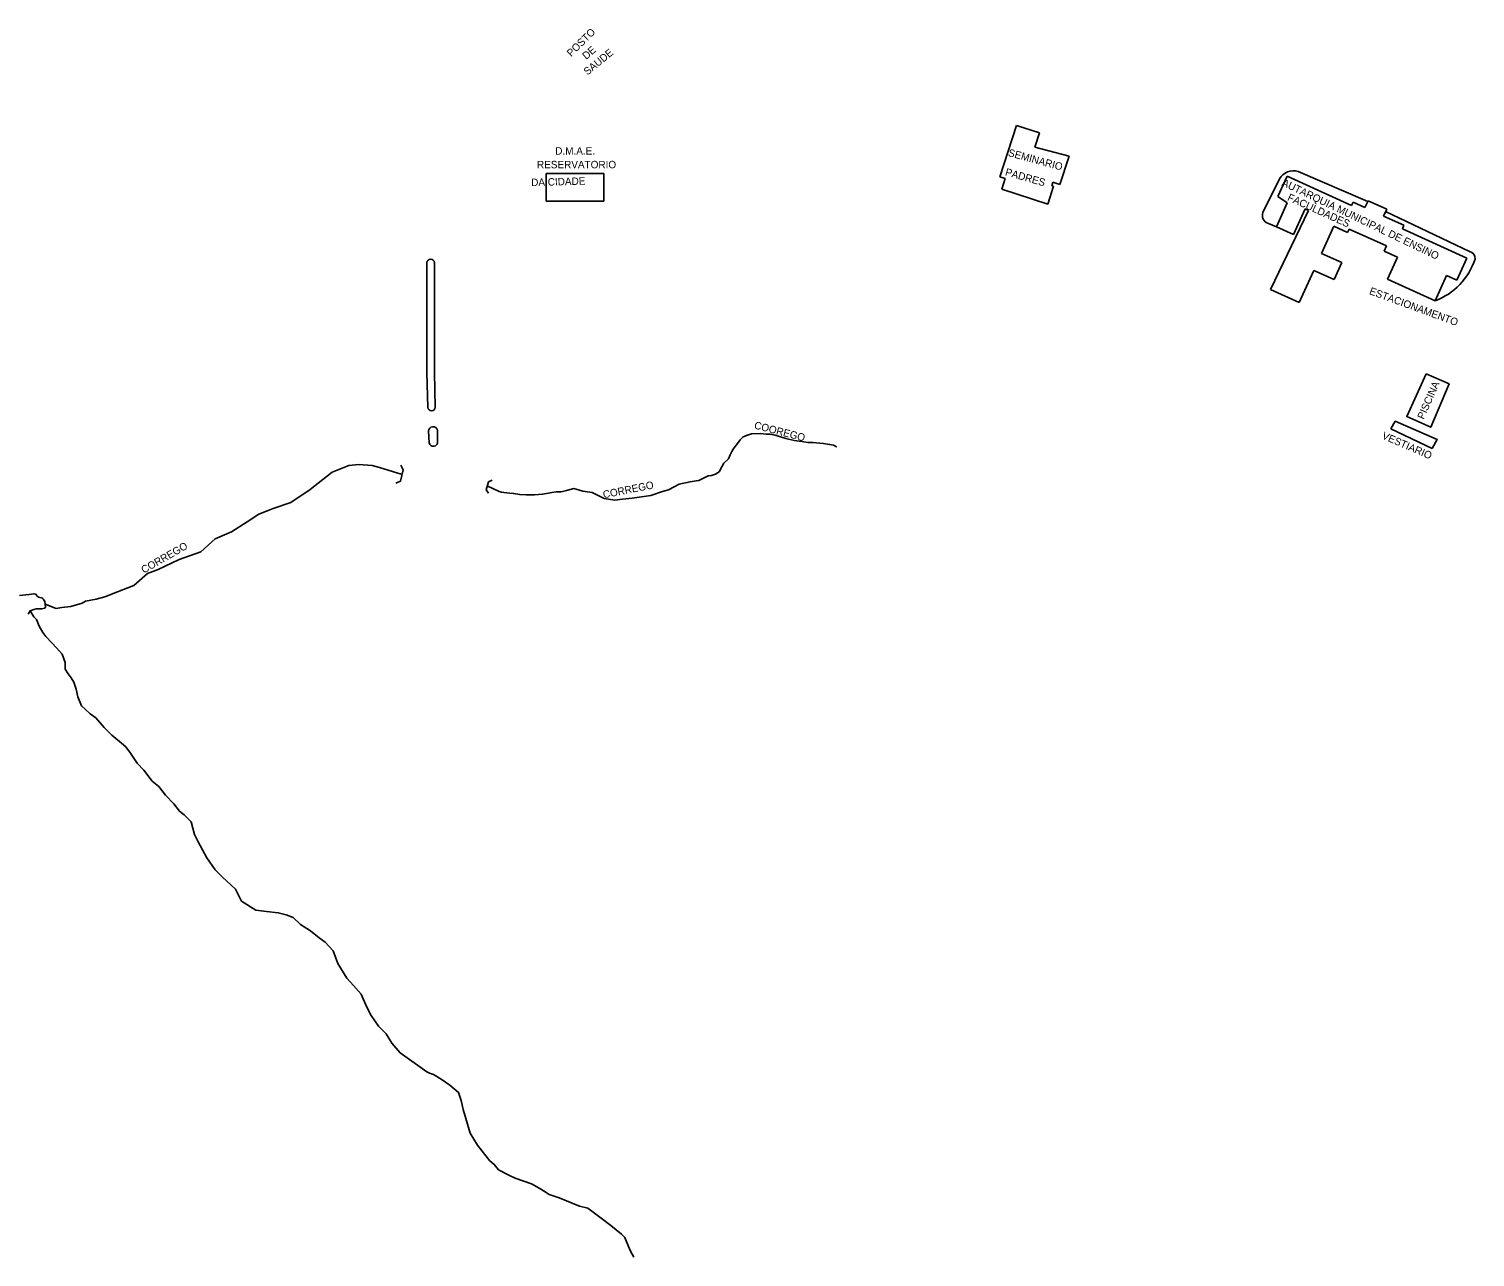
# Model space of a CAD drawing. Extents: x 325899 to 363134, y 7578590 to 7592502.
# Drawn here: x 334117 to 334893, y 7588027 to 7588686 of the extents above; entities that cross this region are included whole.
import ezdxf

# ---------------------------------------------------------------- set-up
doc = ezdxf.new("R2010")
doc.units = 0
for name, color, linetype in [('EDIFEXISTENT', 7, 'Continuous'), ('EDIFIDENTIF', 7, 'Continuous'), ('EDIFOBRAEXIS', 7, 'Continuous')]:
    doc.layers.add(name, color=color, linetype=linetype)

msp = doc.modelspace()

# ---------------------------------------------------------------- linework, layer by layer
at = {"layer": 'EDIFEXISTENT'}
for p, q in [((334638.12, 7588607.06), (334647.04, 7588634.65)), ((334647.04, 7588634.65), (334659.41, 7588630.66)), ((334659.41, 7588630.66), (334656.95, 7588623.04)), ((334656.95, 7588623.04), (334675.33, 7588618.15)), ((334675.33, 7588618.15), (334670.42, 7588602.93)), ((334394.39, 7588608.91), (334425.39, 7588608.91)), ((334394.39, 7588593.91), (334394.39, 7588608.91)), ((334425.39, 7588608.91), (334425.39, 7588593.91)), ((334640.98, 7588606.14), (334638.12, 7588607.06)), ((334639.13, 7588600.43), (334640.98, 7588606.14)), ((334787.52, 7588596.4), (334792.48, 7588607.33)), ((334792.48, 7588607.33), (334827.08, 7588591.6)), ((334663.87, 7588592.43), (334639.13, 7588600.43)), ((334666.95, 7588601.95), (334663.87, 7588592.43)), ((334666.61, 7588604.16), (334665.99, 7588602.26)), ((334665.99, 7588602.26), (334666.95, 7588601.95)), ((334670.42, 7588602.93), (334666.61, 7588604.16)), ((334425.39, 7588593.91), (334394.39, 7588593.91)), ((334786.77, 7588580.26), (334792.56, 7588593.01)), ((334792.56, 7588593.01), (334787.52, 7588596.4)), ((334827.08, 7588591.6), (334827.9, 7588593.42)), ((334827.9, 7588593.42), (334834.28, 7588590.53)), ((334834.28, 7588590.53), (334835.93, 7588594.17)), ((334835.93, 7588594.17), (334845.94, 7588589.62)), ((334783.54, 7588546.58), (334803.9, 7588588.95)), ((334802.08, 7588589.78), (334795.87, 7588576.13)), ((334803.9, 7588588.95), (334802.08, 7588589.78)), ((334845.94, 7588589.62), (334844.29, 7588585.97)), ((334844.29, 7588585.97), (334855.21, 7588581.01)), ((334795.87, 7588576.13), (334786.77, 7588580.26)), ((334817.64, 7588580.51), (334811.02, 7588565.95)), ((334824.92, 7588577.2), (334817.64, 7588580.51)), ((334825.75, 7588579.02), (334824.92, 7588577.2)), ((334845.78, 7588569.92), (334825.75, 7588579.02)), ((334855.21, 7588581.01), (334854.39, 7588579.19)), ((334854.39, 7588579.19), (334888.98, 7588563.46)), ((334844.54, 7588567.19), (334845.78, 7588569.92)), ((334851.82, 7588563.88), (334844.54, 7588567.19)), ((334811.02, 7588565.95), (334821.94, 7588560.98)), ((334821.94, 7588560.98), (334817.81, 7588551.88)), ((334846.44, 7588552.04), (334851.82, 7588563.88)), ((334888.98, 7588563.46), (334883.6, 7588551.63)), ((334806.88, 7588556.84), (334799.02, 7588539.55)), ((334817.81, 7588551.88), (334806.88, 7588556.84)), ((334871.93, 7588540.46), (334846.44, 7588552.04)), ((334878.14, 7588554.11), (334871.93, 7588540.46)), ((334883.6, 7588551.63), (334878.14, 7588554.11)), ((334799.02, 7588539.55), (334783.54, 7588546.58)), ((334316.4, 7588452.25), (334317.61, 7588449.82)), ((334316.16, 7588443.74), (334313.73, 7588442.53)), ((334317.61, 7588449.82), (334316.16, 7588443.74)), ((334362.2, 7588438.93), (334363.56, 7588443.26)), ((334363.56, 7588443.26), (334365.46, 7588444.16)), ((334363.43, 7588437.21), (334362.2, 7588438.93))]:
    msp.add_line(p, q, dxfattribs=at)
at = {"layer": 'EDIFOBRAEXIS'}
for points in [[(334779.39, 7588587.91), (334788.39, 7588605.91)], [(334798.39, 7588609.91), (334835.74, 7588593.75)], [(334845.38, 7588588.37), (334890.39, 7588566.91)], [(334786.77, 7588580.26), (334782.39, 7588581.91)], [(334330.39, 7588501.91), (334330.39, 7588560.91)], [(334334.39, 7588560.91), (334334.39, 7588501.91)], [(334330.39, 7588501.91), (334330.9, 7588483.21)], [(334334.88, 7588483.32), (334334.39, 7588501.91)], [(334867.1, 7588501.36), (334879.43, 7588495.9), (334869.64, 7588472.62), (334856.75, 7588478.3), (334867.1, 7588501.36)], [(334848.15, 7588471.82), (334850.42, 7588475.81), (334872.99, 7588466.11), (334870.41, 7588461.12)], [(334331.59, 7588464.2), (334331.29, 7588470.46)], [(334336.05, 7588470.98), (334336.08, 7588464.9)], [(334481.39, 7588446.54), (334481.46, 7588446.56), (334483.23, 7588446.67), (334483.23, 7588446.67), (334483.23, 7588446.67), (334485.4, 7588447.46), (334485.4, 7588447.46), (334487.29, 7588448.73), (334487.29, 7588448.73), (334488.94, 7588451.64), (334489.94, 7588453.34), (334489.94, 7588453.34), (334492.43, 7588455.63), (334493.25, 7588457.76), (334494.14, 7588459.61), (334495.22, 7588461.31), (334495.22, 7588461.31), (334497.25, 7588463.83), (334497.25, 7588463.83), (334498.6, 7588465.79), (334498.6, 7588465.79), (334500.22, 7588467.48), (334500.22, 7588467.48), (334500.22, 7588467.48), (334502.62, 7588468.27), (334504.83, 7588469.11), (334504.83, 7588469.11), (334509.36, 7588469.24), (334512.67, 7588468.88), (334514.75, 7588468.85), (334517.43, 7588468.38), (334517.43, 7588468.38), (334520.28, 7588467.46), (334523.17, 7588466.56), (334527.72, 7588465.52), (334531.8, 7588464.87), (334535.06, 7588464.49), (334537.61, 7588464.47), (334541.45, 7588464.08), (334543.47, 7588463.87), (334543.47, 7588463.87), (334546.71, 7588463.38), (334546.71, 7588463.38), (334548.75, 7588462.9), (334548.75, 7588462.9), (334550.45, 7588462.15), (334550.45, 7588462.15)], [(334870.41, 7588461.12), (334848.15, 7588471.82)], [(334125.39, 7588377.55), (334131.18, 7588375.24), (334134.37, 7588375.92), (334139.16, 7588376.32), (334145.23, 7588378.15), (334146.93, 7588379.17), (334152.65, 7588380.28), (334157.39, 7588381.57), (334164.17, 7588384.19), (334172.9, 7588387.62), (334180.3, 7588394.02), (334186.04, 7588396.3), (334197.37, 7588401.57), (334208.99, 7588405.76), (334216.59, 7588412.71), (334225.44, 7588416.53), (334233.91, 7588421.91), (334240.13, 7588425.94), (334245.19, 7588427.87), (334247.82, 7588429.05), (334257.29, 7588432.18), (334267.6, 7588439.22), (334271.94, 7588442.56), (334279.42, 7588448.5), (334288.53, 7588452.14), (334293.75, 7588452.6), (334300.95, 7588451.99), (334304.96, 7588451.05), (334316.64, 7588447.39)], [(334362.84, 7588441.15), (334369.12, 7588438.2), (334370.39, 7588437.8), (334371.79, 7588437.63), (334374.88, 7588437.22), (334376.86, 7588437.05), (334380.26, 7588436.43), (334383.76, 7588436.27), (334388.24, 7588436.41), (334392.55, 7588436.64), (334395.77, 7588437.23), (334397.51, 7588437.65), (334399.85, 7588438.01), (334402.48, 7588437.92), (334405.34, 7588438.72), (334409.37, 7588439.68), (334414.19, 7588438.38), (334419.09, 7588437.51), (334425.62, 7588434.37), (334431.3, 7588433.51), (334435.45, 7588433.99), (334440.57, 7588434.52), (334450.7, 7588435.98), (334456.9, 7588438.09), (334460.12, 7588439.07), (334465.91, 7588442.01), (334471.84, 7588443.33), (334475.05, 7588443.82), (334476.52, 7588444.03), (334481.39, 7588446.54)], [(334116.16, 7588372.31), (334117.19, 7588374.12), (334119.17, 7588374.79), (334120.58, 7588375.15), (334121.9, 7588375.13), (334123.6, 7588375.13), (334125.07, 7588375.45), (334125.47, 7588375.93), (334125.39, 7588377.55), (334125.08, 7588379.02), (334124.49, 7588380.11), (334124.06, 7588380.51), (334124.16, 7588380.84), (334121.75, 7588381.31), (334120.81, 7588382.14), (334120.55, 7588382.83), (334120.14, 7588382.98), (334119.31, 7588383.18), (334116.77, 7588382.86), (334111.58, 7588382.23)], [(334117.19, 7588374.12), (334119.23, 7588370.78), (334120.71, 7588369.34), (334122.12, 7588365.88), (334124.14, 7588362.34), (334125.77, 7588360.27), (334128.9, 7588356.86), (334131.45, 7588354.21), (334134.43, 7588350.75), (334136.1, 7588346.27), (334136.16, 7588342.8), (334137.7, 7588340.17), (334139.23, 7588338.09), (334140.73, 7588335.77), (334142.04, 7588332), (334142.85, 7588327.79), (334144.92, 7588323.11), (334146.83, 7588321.32), (334149.45, 7588318.75), (334152.48, 7588316.66), (334156.99, 7588311.41), (334161.06, 7588307.34), (334166.3, 7588303.06), (334168.59, 7588300.96), (334171.14, 7588297.68), (334174.72, 7588292.27), (334178.38, 7588288.43), (334182.84, 7588282.67), (334186.38, 7588279.67), (334190, 7588275.13), (334194.38, 7588270.38), (334197.44, 7588266.49), (334200.01, 7588264.6), (334201.95, 7588262.58), (334203.75, 7588260.74), (334205.58, 7588253.93), (334207.58, 7588250.06), (334212.2, 7588241.49), (334216.59, 7588234.99), (334220.34, 7588231.16), (334227.61, 7588224.62), (334230.76, 7588218.2), (334238.56, 7588213.39), (334244.17, 7588212.58), (334250.56, 7588211.95), (334254.77, 7588210.83), (334258.46, 7588209.35), (334262.53, 7588205.72), (334267.92, 7588202.22), (334272.47, 7588198.54), (334275.73, 7588196.19), (334280.11, 7588191.52), (334282.57, 7588184.67), (334287.42, 7588176.8), (334291.01, 7588172.89), (334295.14, 7588168.32), (334297.96, 7588161.62), (334300.41, 7588156.84), (334304.37, 7588151.1), (334308.52, 7588146.91), (334311.51, 7588141.96), (334316.07, 7588136.68), (334330.38, 7588126.6), (334331.75, 7588125.9), (334333.84, 7588125.05), (334338.08, 7588122.68), (334342.78, 7588119.43), (334347.36, 7588115.55), (334348.88, 7588111.15), (334349.79, 7588106.41), (334353.67, 7588093.63), (334357.58, 7588087.18), (334360, 7588083.9), (334363.98, 7588079), (334366.73, 7588076.65), (334368.89, 7588074), (334374.74, 7588070.93), (334377.73, 7588069.5), (334386.49, 7588066.35), (334390.74, 7588064.16), (334393.84, 7588062.15), (334396.1, 7588060.79), (334401.38, 7588058.83), (334412.4, 7588054.47), (334416.79, 7588053.38), (334423.2, 7588048.46), (334429.1, 7588044.13), (334434.88, 7588039.41), (334436.66, 7588037.6), (334438.63, 7588032.81), (334439.78, 7588030.26), (334441.6, 7588027.12)]]:
    msp.add_lwpolyline(points, dxfattribs=at)
for centre, radius, start, end in [((334795.89, 7588601.66), 8.62, 73.1416, 150.46122), ((334783.89, 7588586.41), 4.74, 161.56505, 251.56505), ((334889.89, 7588563.41), 3.54, 351.86991, 81.86989), ((334332.39, 7588560.89), 2, 0.74239, 179.25761), ((334859.28, 7588574.03), 35.88, 290.65196, 341.94787), ((334332.89, 7588483.41), 1.99, 185.6771, 357.47528), ((334333.69, 7588470.53), 2.4, 10.89556, 181.75931), ((334333.82, 7588464.62), 2.27, 190.67525, 7.18106)]:
    msp.add_arc(centre, radius, start, end, dxfattribs=at)

# ---------------------------------------------------------------- texts
at = {"layer": 'EDIFIDENTIF'}
for s, rotation, p in [('POSTO', 44.43096, (334407.87, 7588671.26)), ('DE', 40.78763, (334415.95, 7588669.76)), ('SAUDE', 39.30346, (334416.62, 7588661.37)), ('SEMINARIO', 344.77482, (334642.28, 7588618.26)), ('DA CIDADE', 1.63658, (334386.45, 7588602.03)), ('PADRES', 344.07641, (334640.72, 7588607.92)), ('AUTARQUIA MUNICIPAL DE ENSINO', 334.35899, (334789.24, 7588602.54)), ('FACULDADES', 335.63755, (334792.26, 7588594.58)), ('ESTACIONAMENTO', 339.88408, (334836.27, 7588544.15)), ('PISCINA', 66.46548, (334865.85, 7588476.53)), ('COOREGO', 345.4413, (334505.91, 7588471.98)), ('VESTIARIO', 336.46548, (334843.04, 7588466.64)), ('CORREGO', 11.3025, (334425.35, 7588434.42)), ('CORREGO', 29.9649, (334178.36, 7588393.96))]:
    msp.add_text(s, height=4, rotation=rotation, dxfattribs=at).set_placement(p)
for s, p in [('D.M.A.E.', (334399.33, 7588618.95)), ('RESERVATORIO', (334389.52, 7588611.62))]:
    msp.add_text(s, height=4, dxfattribs=at).set_placement(p)

doc.saveas('drawing.dxf')
